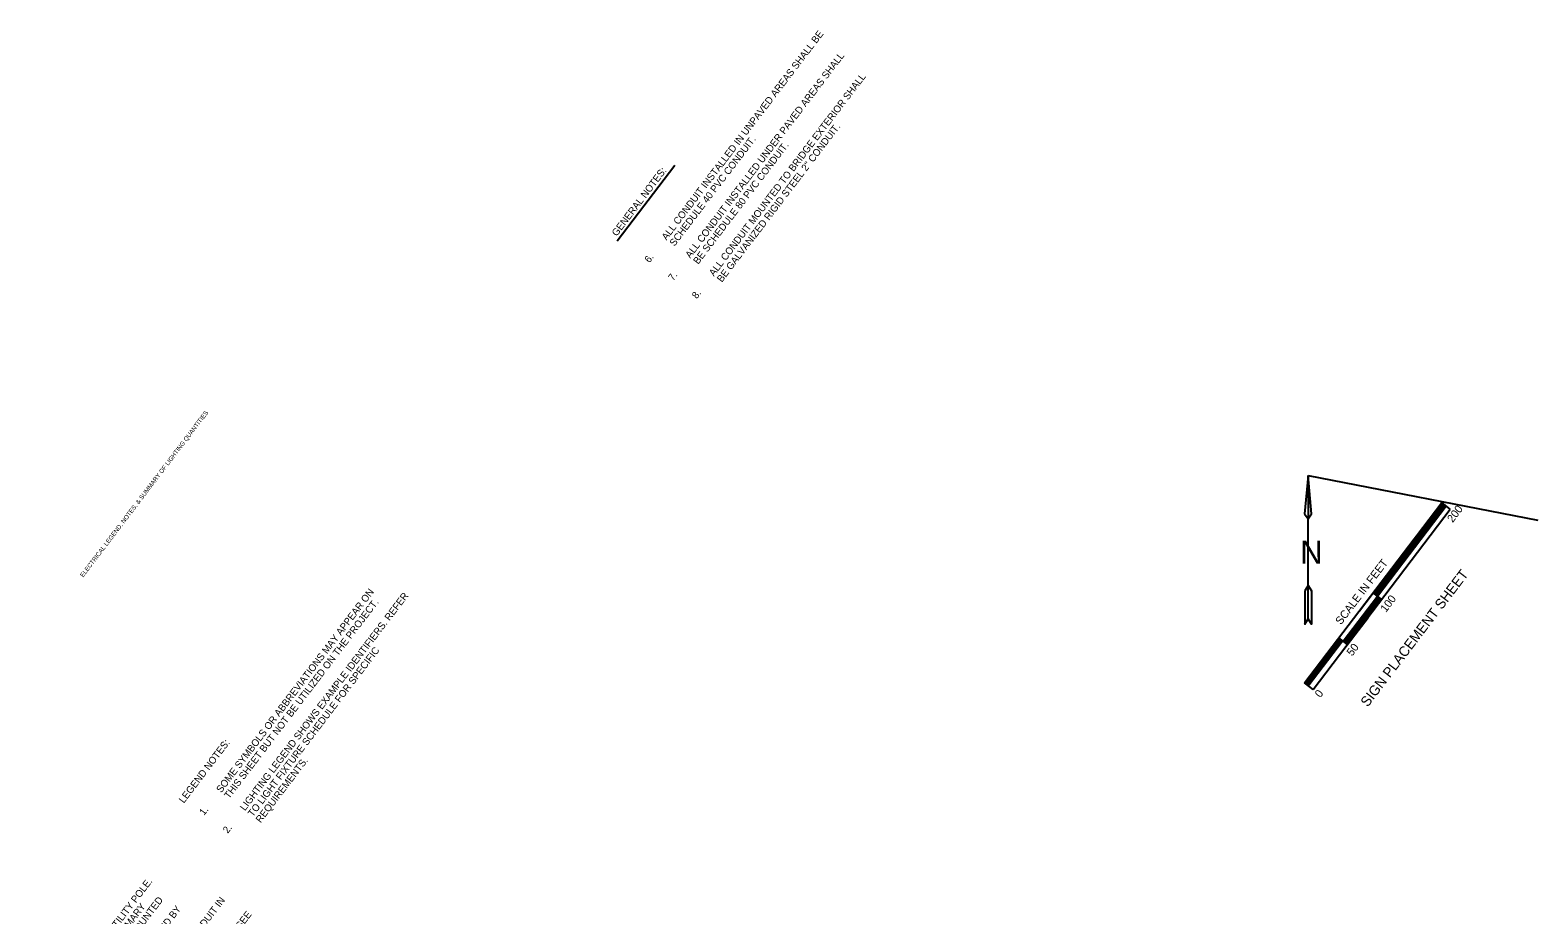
# Model space of a CAD drawing. Extents: x 1289840 to 1300655, y 220865 to 232830.
# Drawn here: x 1299324 to 1300655, y 232049 to 232830 of the extents above; entities that cross this region are included whole.
import ezdxf

# ---------------------------------------------------------------- set-up
doc = ezdxf.new("R2010")
doc.units = 0
for name, color, linetype in [('60', 7, 'Continuous'), ('E-ANNO-NOTE', 7, 'Continuous'), ('G-ANNO-TEXT', 7, 'Continuous'), ('Level 10', 7, 'Continuous'), ('Plan Notes', 7, 'Continuous'), ('R_Border', 7, 'Continuous'), ('R_No Plot', 7, 'Continuous')]:
    doc.layers.add(name, color=color, linetype=linetype)

msp = doc.modelspace()

# ---------------------------------------------------------------- linework, layer by layer
at = {"layer": '60'}
msp.add_line((1300654.5, 232397.3), (1300654.5, 232397.3), dxfattribs=at)
at = {"layer": 'E-ANNO-NOTE'}
msp.add_line((1299842.2, 232644.2), (1299892.9, 232710.8), dxfattribs=at)
at = {"layer": 'G-ANNO-TEXT'}
for p, q in [((1300451.8, 232437), (1300448.6, 232403)), ((1300448.6, 232403), (1300451.8, 232398.5)), ((1300451.8, 232339.7), (1300451.8, 232398.6))]:
    msp.add_line(p, q, dxfattribs=at)
for points in [[(1300451.8, 232436.9), (1300451.8, 232398.5), (1300454.9, 232403)], [(1300448.9, 232335), (1300448.9, 232305.5), (1300451.8, 232310.4), (1300451.8, 232339.7)], [(1300451.8, 232339.7), (1300454.7, 232335), (1300454.7, 232305.5), (1300451.8, 232310.4)]]:
    msp.add_lwpolyline(points, close=True, dxfattribs=at)
at = {"layer": 'Level 10'}
for p, q in [((1300456.3, 232247.8), (1300577.3, 232407.1)), ((1300497.1, 232317.3), (1300569.7, 232412.9)), ((1300509.8, 232332.8), (1300570.3, 232412.4)), ((1300510.4, 232332.3), (1300571, 232411.9)), ((1300511.1, 232331.8), (1300571.6, 232411.4)), ((1300511.7, 232331.3), (1300572.2, 232410.9)), ((1300512.4, 232330.8), (1300572.9, 232410.5)), ((1300513, 232330.4), (1300573.5, 232410)), ((1300577.3, 232407.1), (1300569.7, 232412.9)), ((1300448.7, 232253.7), (1300545.5, 232381)), ((1300513, 232330.4), (1300549.3, 232378.1)), ((1300482.7, 232290.6), (1300513, 232330.4)), ((1300483.4, 232290.1), (1300513.6, 232329.9)), ((1300484, 232289.6), (1300514.3, 232329.4)), ((1300484.7, 232289.1), (1300514.9, 232328.9)), ((1300485.3, 232288.6), (1300515.5, 232328.4)), ((1300485.9, 232288.1), (1300516.2, 232327.9)), ((1300516.8, 232327.4), (1300509.2, 232333.3)), ((1300480.5, 232279.7), (1300504.7, 232311.5)), ((1300448.7, 232253.7), (1300472.9, 232285.5)), ((1300449.3, 232253.2), (1300479.6, 232293)), ((1300449.9, 232252.7), (1300480.2, 232292.5)), ((1300450.6, 232252.2), (1300480.8, 232292)), ((1300451.2, 232251.7), (1300481.5, 232291.5)), ((1300451.8, 232251.2), (1300482.1, 232291)), ((1300486.6, 232287.6), (1300478.9, 232293.5)), ((1300456.3, 232247.8), (1300448.7, 232253.7))]:
    msp.add_line(p, q, dxfattribs=at)
at = {"layer": 'Plan Notes'}
msp.add_line((1300654.5, 232397.3), (1300654.5, 232397.3), dxfattribs=at)
msp.add_line((1300654.5, 232397.3), (1300654.5, 232397.3), dxfattribs=at)
at = {"layer": 'R_No Plot'}
msp.add_line((1300451.8, 232437), (1300654.5, 232397.3), dxfattribs=at)

# ---------------------------------------------------------------- texts
at = {"layer": '60'}
msp.add_text('SIGN PLACEMENT SHEET', height=8.87, rotation=52.7501, dxfattribs=at).set_placement((1300504.4, 232231.9))
at = {"layer": 'E-ANNO-NOTE'}
for s, rotation, p in [('ALL CONDUIT INSTALLED IN UNPAVED AREAS SHALL BE ', 52.7501, (1299885.7, 232644.1)), ('ALL CONDUIT INSTALLED UNDER PAVED AREAS SHALL ', 52.7501, (1299906.6, 232628.2)), ('ALL CONDUIT MOUNTED TO BRIDGE EXTERIOR SHALL ', 52.7501, (1299927.5, 232612.3)), ('SCHEDULE 40 PVC CONDUIT.', 52.7501, (1299892.7, 232638.8)), ('BE GALVANIZED RIGID STEEL 2" CONDUIT.', 52.7501, (1299934.5, 232607)), ('BE SCHEDULE 80 PVC CONDUIT.', 52.7501, (1299913.6, 232622.9)), ('GENERAL NOTES:', 52.7952, (1299841.7, 232647.6)), ('6.', 52.7501, (1299870.6, 232624.2)), ('7.', 52.7501, (1299891.5, 232608.3)), ('8.', 52.7501, (1299912.4, 232592.4)), ('SOME SYMBOLS OR ABBREVIATIONS MAY APPEAR ON ', 52.7501, (1299492.7, 232156.2)), ('THIS SHEET BUT NOT BE UTILIZED ON THE PROJECT.', 52.7501, (1299499.7, 232150.9)), ('LIGHTING LEGEND SHOWS EXAMPLE IDENTIFIERS. REFER ', 52.7501, (1299513.6, 232140.3)), ('TO LIGHT FIXTURE SCHEDULE FOR SPECIFIC ', 52.7501, (1299520.6, 232135)), ('LEGEND NOTES:', 52.7502, (1299459.7, 232147)), ('REQUIREMENTS.', 52.7501, (1299527.5, 232129.7)), ('1.', 52.7501, (1299477.6, 232136.3)), ('2.', 52.7501, (1299498.5, 232120.4)), ('STUB-UP CONDUIT AT NEW UTILITY POLE. ', 52.7501, (1299328.1, 231941.4)), ('UTILITY TO CONNECT NEW PRIMARY ', 52.7501, (1299335, 231936.1)), ('CONDUCTORS TO NEW POLE MOUNTED ', 52.7501, (1299342, 231930.8)), ('TRANSFORMER SHALL BE INSTALLED BY ', 52.7501, (1299355.9, 231920.2)), ('TRANSITION FROM UNDERGROUND CONDUIT IN ', 52.7501, (1299376.8, 231904.3)), ('NECESSARY TO MEET NEC REQUIREMENTS. SEE ', 52.7501, (1299397.7, 231888.4))]:
    msp.add_text(s, height=6.25, rotation=rotation, dxfattribs=at).set_placement(p)
at = {"layer": 'G-ANNO-TEXT'}
msp.add_text('N', height=20.4, rotation=0.0088, dxfattribs=at).set_placement((1300444.9, 232358.9))
at = {"layer": 'Level 10'}
for s, height, p in [('200', 7, (1300579.4, 232394.8)), ('SCALE IN FEET', 7.001, (1300480.8, 232304.5)), ('100', 7, (1300520.5, 232315.5)), ('50', 7, (1300490.7, 232276.9)), ('0', 7, (1300462.6, 232240.2))]:
    msp.add_text(s, height=height, rotation=52.7639, dxfattribs=at).set_placement(p)
at = {"layer": 'R_Border'}
msp.add_text('ELECTRICAL LEGEND, NOTES, & SUMMARY OF LIGHTING QUANTITIES', height=3.881, rotation=52.7519, dxfattribs=at).set_placement((1299370.9, 232346.7))

doc.saveas('drawing.dxf')
